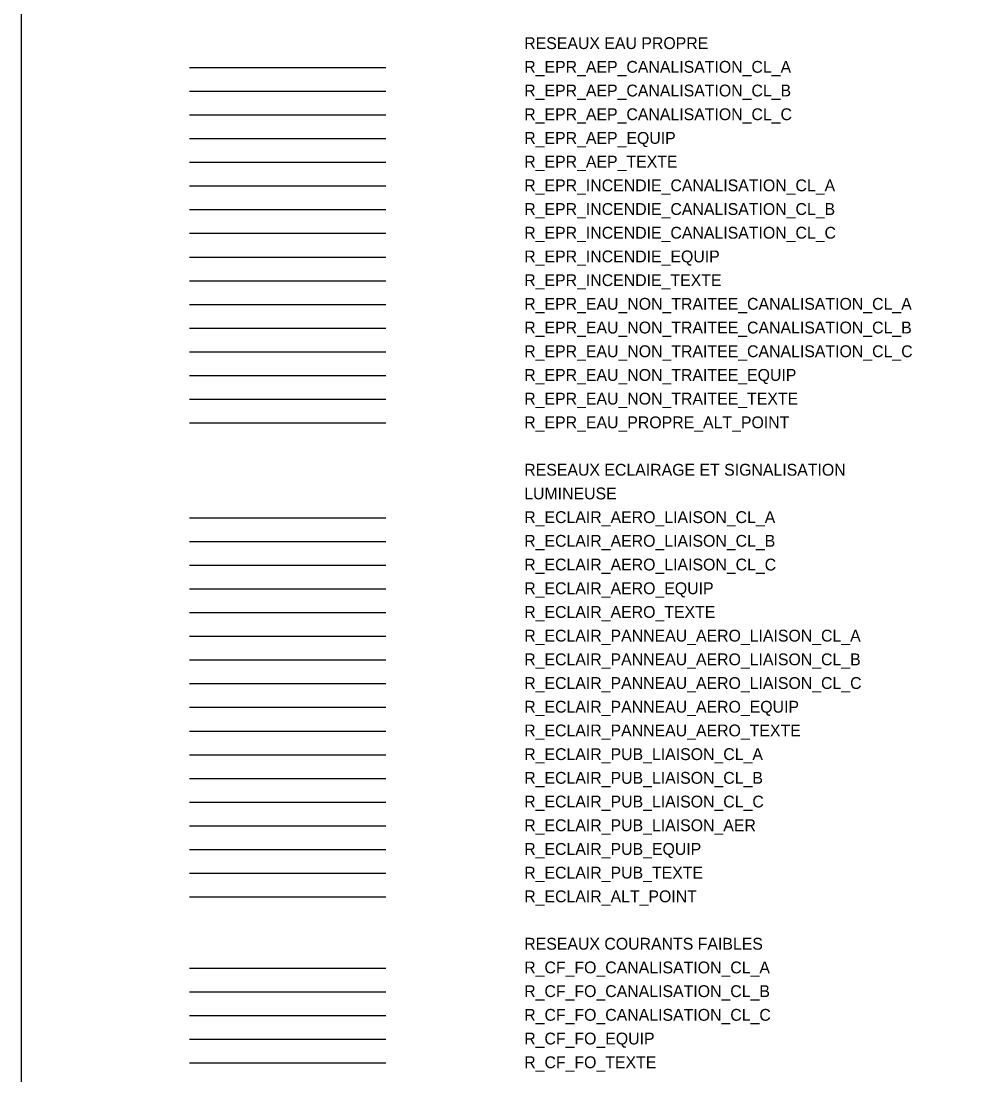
# Model space of a CAD drawing. Extents: x -60 to 214, y -380 to -21.
# Drawn here: x 33.07 to 72.77, y -245.94 to -201.47 of the extents above; entities that cross this region are included whole.
import ezdxf

# ---------------------------------------------------------------- set-up
doc = ezdxf.new("R2010")
doc.units = 0
for name, color, linetype in [('Default', 7, 'Continuous'), ('DH_TEXTE', 7, 'Continuous'), ('R_CF_FO_CANALISATION_CL_A', 7, 'Continuous'), ('R_CF_FO_CANALISATION_CL_B', 7, 'Continuous'), ('R_CF_FO_CANALISATION_CL_C', 7, 'Continuous'), ('R_CF_FO_EQUIP', 7, 'Continuous'), ('R_CF_FO_TEXTE', 7, 'Continuous'), ('R_ECLAIR_AERO_EQUIP', 7, 'Continuous'), ('R_ECLAIR_AERO_LIAISON_CL_A', 7, 'Continuous'), ('R_ECLAIR_AERO_LIAISON_CL_B', 7, 'Continuous'), ('R_ECLAIR_AERO_LIAISON_CL_C', 7, 'Continuous'), ('R_ECLAIR_AERO_TEXTE', 7, 'Continuous'), ('R_ECLAIR_ALT_POINT', 7, 'Continuous'), ('R_ECLAIR_PANNEAU_AERO_EQUIP', 7, 'Continuous'), ('R_ECLAIR_PANNEAU_AERO_LIAISON_CL_A', 7, 'Continuous'), ('R_ECLAIR_PANNEAU_AERO_LIAISON_CL_B', 7, 'Continuous'), ('R_ECLAIR_PANNEAU_AERO_LIAISON_CL_C', 7, 'Continuous'), ('R_ECLAIR_PANNEAU_AERO_TEXTE', 7, 'Continuous'), ('R_ECLAIR_PUB_EQUIP', 7, 'Continuous'), ('R_ECLAIR_PUB_LIAISON_CL_A', 7, 'Continuous'), ('R_ECLAIR_PUB_LIAISON_CL_B', 7, 'Continuous'), ('R_ECLAIR_PUB_LIAISON_CL_C', 7, 'Continuous'), ('R_ECLAIR_PUB_TEXTE', 7, 'Continuous'), ('R_EPR_AEP_CANALISATION_CL_A', 7, 'Continuous'), ('R_EPR_AEP_CANALISATION_CL_B', 7, 'Continuous'), ('R_EPR_AEP_CANALISATION_CL_C', 7, 'Continuous'), ('R_EPR_AEP_EQUIP', 7, 'Continuous'), ('R_EPR_AEP_TEXTE', 7, 'Continuous'), ('R_EPR_EAU_NON_TRAITEE_CANALISATION_CL_A', 7, 'Continuous'), ('R_EPR_EAU_NON_TRAITEE_CANALISATION_CL_B', 7, 'Continuous'), ('R_EPR_EAU_NON_TRAITEE_CANALISATION_CL_C', 7, 'Continuous'), ('R_EPR_EAU_NON_TRAITEE_EQUIP', 7, 'Continuous'), ('R_EPR_EAU_NON_TRAITEE_TEXTE', 7, 'Continuous'), ('R_EPR_EAU_PROPRE_ALT_POINT', 7, 'Continuous'), ('R_EPR_INCENDIE_CANALISATION_CL_A', 7, 'Continuous'), ('R_EPR_INCENDIE_CANALISATION_CL_B', 7, 'Continuous'), ('R_EPR_INCENDIE_CANALISATION_CL_C', 7, 'Continuous'), ('R_EPR_INCENDIE_EQUIP', 7, 'Continuous'), ('R_EPR_INCENDIE_TEXTE', 7, 'Continuous')]:
    doc.layers.add(name, color=color, linetype=linetype)

msp = doc.modelspace()

# ---------------------------------------------------------------- linework, layer by layer
at = {"layer": 'Default'}
msp.add_line((40.178, -235.429), (48.457, -235.429), dxfattribs=at)
msp.add_lwpolyline([(114.838, -25.727), (33.073, -25.727), (33.073, -380.216), (114.838, -380.216)], close=True, dxfattribs=at)
at = {"layer": 'R_CF_FO_CANALISATION_CL_A'}
msp.add_line((40.178, -241.429), (48.457, -241.429), dxfattribs=at)
at = {"layer": 'R_CF_FO_CANALISATION_CL_B'}
msp.add_line((40.178, -242.429), (48.457, -242.429), dxfattribs=at)
at = {"layer": 'R_CF_FO_CANALISATION_CL_C'}
msp.add_line((40.178, -243.429), (48.457, -243.429), dxfattribs=at)
at = {"layer": 'R_CF_FO_EQUIP'}
msp.add_line((40.178, -244.429), (48.457, -244.429), dxfattribs=at)
at = {"layer": 'R_CF_FO_TEXTE'}
msp.add_line((40.178, -245.429), (48.457, -245.429), dxfattribs=at)
at = {"layer": 'R_ECLAIR_AERO_EQUIP'}
msp.add_line((40.178, -225.429), (48.457, -225.429), dxfattribs=at)
at = {"layer": 'R_ECLAIR_AERO_LIAISON_CL_A'}
msp.add_line((40.178, -222.429), (48.457, -222.429), dxfattribs=at)
at = {"layer": 'R_ECLAIR_AERO_LIAISON_CL_B'}
msp.add_line((40.178, -223.429), (48.457, -223.429), dxfattribs=at)
at = {"layer": 'R_ECLAIR_AERO_LIAISON_CL_C'}
msp.add_line((40.178, -224.429), (48.457, -224.429), dxfattribs=at)
at = {"layer": 'R_ECLAIR_AERO_TEXTE'}
msp.add_line((40.178, -226.429), (48.457, -226.429), dxfattribs=at)
at = {"layer": 'R_ECLAIR_ALT_POINT'}
msp.add_line((40.178, -238.429), (48.457, -238.429), dxfattribs=at)
at = {"layer": 'R_ECLAIR_PANNEAU_AERO_EQUIP'}
msp.add_line((40.178, -230.429), (48.457, -230.429), dxfattribs=at)
at = {"layer": 'R_ECLAIR_PANNEAU_AERO_LIAISON_CL_A'}
msp.add_line((40.178, -227.429), (48.457, -227.429), dxfattribs=at)
at = {"layer": 'R_ECLAIR_PANNEAU_AERO_LIAISON_CL_B'}
msp.add_line((40.178, -228.429), (48.457, -228.429), dxfattribs=at)
at = {"layer": 'R_ECLAIR_PANNEAU_AERO_LIAISON_CL_C'}
msp.add_line((40.178, -229.429), (48.457, -229.429), dxfattribs=at)
at = {"layer": 'R_ECLAIR_PANNEAU_AERO_TEXTE'}
msp.add_line((40.178, -231.429), (48.457, -231.429), dxfattribs=at)
at = {"layer": 'R_ECLAIR_PUB_EQUIP'}
msp.add_line((40.178, -236.429), (48.457, -236.429), dxfattribs=at)
at = {"layer": 'R_ECLAIR_PUB_LIAISON_CL_A'}
msp.add_line((40.178, -232.429), (48.457, -232.429), dxfattribs=at)
at = {"layer": 'R_ECLAIR_PUB_LIAISON_CL_B'}
msp.add_line((40.178, -233.429), (48.457, -233.429), dxfattribs=at)
at = {"layer": 'R_ECLAIR_PUB_LIAISON_CL_C'}
msp.add_line((40.178, -234.429), (48.457, -234.429), dxfattribs=at)
at = {"layer": 'R_ECLAIR_PUB_TEXTE'}
msp.add_line((40.178, -237.429), (48.457, -237.429), dxfattribs=at)
at = {"layer": 'R_EPR_AEP_CANALISATION_CL_A'}
msp.add_line((40.178, -203.429), (48.457, -203.429), dxfattribs=at)
at = {"layer": 'R_EPR_AEP_CANALISATION_CL_B'}
msp.add_line((40.178, -204.429), (48.457, -204.429), dxfattribs=at)
at = {"layer": 'R_EPR_AEP_CANALISATION_CL_C'}
msp.add_line((40.178, -205.429), (48.457, -205.429), dxfattribs=at)
at = {"layer": 'R_EPR_AEP_EQUIP'}
msp.add_line((40.178, -206.429), (48.457, -206.429), dxfattribs=at)
at = {"layer": 'R_EPR_AEP_TEXTE'}
msp.add_line((40.178, -207.429), (48.457, -207.429), dxfattribs=at)
at = {"layer": 'R_EPR_EAU_NON_TRAITEE_CANALISATION_CL_A'}
msp.add_line((40.178, -213.429), (48.457, -213.429), dxfattribs=at)
at = {"layer": 'R_EPR_EAU_NON_TRAITEE_CANALISATION_CL_B'}
msp.add_line((40.178, -214.429), (48.457, -214.429), dxfattribs=at)
at = {"layer": 'R_EPR_EAU_NON_TRAITEE_CANALISATION_CL_C'}
msp.add_line((40.178, -215.429), (48.457, -215.429), dxfattribs=at)
at = {"layer": 'R_EPR_EAU_NON_TRAITEE_EQUIP'}
msp.add_line((40.178, -216.429), (48.457, -216.429), dxfattribs=at)
at = {"layer": 'R_EPR_EAU_NON_TRAITEE_TEXTE'}
msp.add_line((40.178, -217.429), (48.457, -217.429), dxfattribs=at)
at = {"layer": 'R_EPR_EAU_PROPRE_ALT_POINT'}
msp.add_line((40.178, -218.429), (48.457, -218.429), dxfattribs=at)
at = {"layer": 'R_EPR_INCENDIE_CANALISATION_CL_A'}
msp.add_line((40.178, -208.429), (48.457, -208.429), dxfattribs=at)
at = {"layer": 'R_EPR_INCENDIE_CANALISATION_CL_B'}
msp.add_line((40.178, -209.429), (48.457, -209.429), dxfattribs=at)
at = {"layer": 'R_EPR_INCENDIE_CANALISATION_CL_C'}
msp.add_line((40.178, -210.429), (48.457, -210.429), dxfattribs=at)
at = {"layer": 'R_EPR_INCENDIE_EQUIP'}
msp.add_line((40.178, -211.429), (48.457, -211.429), dxfattribs=at)
at = {"layer": 'R_EPR_INCENDIE_TEXTE'}
msp.add_line((40.178, -212.429), (48.457, -212.429), dxfattribs=at)

# ---------------------------------------------------------------- texts
at = {"layer": 'DH_TEXTE'}
for s, p in [('RESEAUX EAU PROPRE ', (54.301, -202.655)), ('RESEAUX ECLAIRAGE ET SIGNALISATION ', (54.301, -220.655)), ('LUMINEUSE ', (54.301, -221.655)), ('R_ECLAIR_PUB_LIAISON_AER ', (54.301, -235.655)), ('RESEAUX COURANTS FAIBLES ', (54.301, -240.655))]:
    msp.add_text(s, height=0.5, dxfattribs=at).set_placement(p)
at = {"layer": 'R_CF_FO_CANALISATION_CL_A'}
msp.add_text('R_CF_FO_CANALISATION_CL_A ', height=0.5, dxfattribs=at).set_placement((54.301, -241.655))
at = {"layer": 'R_CF_FO_CANALISATION_CL_B'}
msp.add_text('R_CF_FO_CANALISATION_CL_B ', height=0.5, dxfattribs=at).set_placement((54.301, -242.655))
at = {"layer": 'R_CF_FO_CANALISATION_CL_C'}
msp.add_text('R_CF_FO_CANALISATION_CL_C ', height=0.5, dxfattribs=at).set_placement((54.301, -243.655))
at = {"layer": 'R_CF_FO_EQUIP'}
msp.add_text('R_CF_FO_EQUIP ', height=0.5, dxfattribs=at).set_placement((54.301, -244.655))
at = {"layer": 'R_CF_FO_TEXTE'}
msp.add_text('R_CF_FO_TEXTE ', height=0.5, dxfattribs=at).set_placement((54.301, -245.655))
at = {"layer": 'R_ECLAIR_AERO_EQUIP'}
msp.add_text('R_ECLAIR_AERO_EQUIP ', height=0.5, dxfattribs=at).set_placement((54.301, -225.655))
at = {"layer": 'R_ECLAIR_AERO_LIAISON_CL_A'}
msp.add_text('R_ECLAIR_AERO_LIAISON_CL_A ', height=0.5, dxfattribs=at).set_placement((54.301, -222.655))
at = {"layer": 'R_ECLAIR_AERO_LIAISON_CL_B'}
msp.add_text('R_ECLAIR_AERO_LIAISON_CL_B ', height=0.5, dxfattribs=at).set_placement((54.301, -223.655))
at = {"layer": 'R_ECLAIR_AERO_LIAISON_CL_C'}
msp.add_text('R_ECLAIR_AERO_LIAISON_CL_C ', height=0.5, dxfattribs=at).set_placement((54.301, -224.655))
at = {"layer": 'R_ECLAIR_AERO_TEXTE'}
msp.add_text('R_ECLAIR_AERO_TEXTE ', height=0.5, dxfattribs=at).set_placement((54.301, -226.655))
at = {"layer": 'R_ECLAIR_ALT_POINT'}
msp.add_text('R_ECLAIR_ALT_POINT  ', height=0.5, dxfattribs=at).set_placement((54.301, -238.655))
at = {"layer": 'R_ECLAIR_PANNEAU_AERO_EQUIP'}
msp.add_text('R_ECLAIR_PANNEAU_AERO_EQUIP ', height=0.5, dxfattribs=at).set_placement((54.301, -230.655))
at = {"layer": 'R_ECLAIR_PANNEAU_AERO_LIAISON_CL_A'}
msp.add_text('R_ECLAIR_PANNEAU_AERO_LIAISON_CL_A ', height=0.5, dxfattribs=at).set_placement((54.301, -227.655))
at = {"layer": 'R_ECLAIR_PANNEAU_AERO_LIAISON_CL_B'}
msp.add_text('R_ECLAIR_PANNEAU_AERO_LIAISON_CL_B ', height=0.5, dxfattribs=at).set_placement((54.301, -228.655))
at = {"layer": 'R_ECLAIR_PANNEAU_AERO_LIAISON_CL_C'}
msp.add_text('R_ECLAIR_PANNEAU_AERO_LIAISON_CL_C ', height=0.5, dxfattribs=at).set_placement((54.301, -229.655))
at = {"layer": 'R_ECLAIR_PANNEAU_AERO_TEXTE'}
msp.add_text('R_ECLAIR_PANNEAU_AERO_TEXTE ', height=0.5, dxfattribs=at).set_placement((54.301, -231.655))
at = {"layer": 'R_ECLAIR_PUB_EQUIP'}
msp.add_text('R_ECLAIR_PUB_EQUIP ', height=0.5, dxfattribs=at).set_placement((54.301, -236.655))
at = {"layer": 'R_ECLAIR_PUB_LIAISON_CL_A'}
msp.add_text('R_ECLAIR_PUB_LIAISON_CL_A ', height=0.5, dxfattribs=at).set_placement((54.301, -232.655))
at = {"layer": 'R_ECLAIR_PUB_LIAISON_CL_B'}
msp.add_text('R_ECLAIR_PUB_LIAISON_CL_B ', height=0.5, dxfattribs=at).set_placement((54.301, -233.655))
at = {"layer": 'R_ECLAIR_PUB_LIAISON_CL_C'}
msp.add_text('R_ECLAIR_PUB_LIAISON_CL_C ', height=0.5, dxfattribs=at).set_placement((54.301, -234.655))
at = {"layer": 'R_ECLAIR_PUB_TEXTE'}
msp.add_text('R_ECLAIR_PUB_TEXTE ', height=0.5, dxfattribs=at).set_placement((54.301, -237.655))
at = {"layer": 'R_EPR_AEP_CANALISATION_CL_A'}
msp.add_text('R_EPR_AEP_CANALISATION_CL_A ', height=0.5, dxfattribs=at).set_placement((54.301, -203.655))
at = {"layer": 'R_EPR_AEP_CANALISATION_CL_B'}
msp.add_text('R_EPR_AEP_CANALISATION_CL_B ', height=0.5, dxfattribs=at).set_placement((54.301, -204.655))
at = {"layer": 'R_EPR_AEP_CANALISATION_CL_C'}
msp.add_text('R_EPR_AEP_CANALISATION_CL_C ', height=0.5, dxfattribs=at).set_placement((54.301, -205.655))
at = {"layer": 'R_EPR_AEP_EQUIP'}
msp.add_text('R_EPR_AEP_EQUIP ', height=0.5, dxfattribs=at).set_placement((54.301, -206.655))
at = {"layer": 'R_EPR_AEP_TEXTE'}
msp.add_text('R_EPR_AEP_TEXTE ', height=0.5, dxfattribs=at).set_placement((54.301, -207.655))
at = {"layer": 'R_EPR_EAU_NON_TRAITEE_CANALISATION_CL_A'}
msp.add_text('R_EPR_EAU_NON_TRAITEE_CANALISATION_CL_A ', height=0.5, dxfattribs=at).set_placement((54.301, -213.655))
at = {"layer": 'R_EPR_EAU_NON_TRAITEE_CANALISATION_CL_B'}
msp.add_text('R_EPR_EAU_NON_TRAITEE_CANALISATION_CL_B ', height=0.5, dxfattribs=at).set_placement((54.301, -214.655))
at = {"layer": 'R_EPR_EAU_NON_TRAITEE_CANALISATION_CL_C'}
msp.add_text('R_EPR_EAU_NON_TRAITEE_CANALISATION_CL_C ', height=0.5, dxfattribs=at).set_placement((54.301, -215.655))
at = {"layer": 'R_EPR_EAU_NON_TRAITEE_EQUIP'}
msp.add_text('R_EPR_EAU_NON_TRAITEE_EQUIP ', height=0.5, dxfattribs=at).set_placement((54.301, -216.655))
at = {"layer": 'R_EPR_EAU_NON_TRAITEE_TEXTE'}
msp.add_text('R_EPR_EAU_NON_TRAITEE_TEXTE ', height=0.5, dxfattribs=at).set_placement((54.301, -217.655))
at = {"layer": 'R_EPR_EAU_PROPRE_ALT_POINT'}
msp.add_text('R_EPR_EAU_PROPRE_ALT_POINT  ', height=0.5, dxfattribs=at).set_placement((54.301, -218.655))
at = {"layer": 'R_EPR_INCENDIE_CANALISATION_CL_A'}
msp.add_text('R_EPR_INCENDIE_CANALISATION_CL_A ', height=0.5, dxfattribs=at).set_placement((54.301, -208.655))
at = {"layer": 'R_EPR_INCENDIE_CANALISATION_CL_B'}
msp.add_text('R_EPR_INCENDIE_CANALISATION_CL_B ', height=0.5, dxfattribs=at).set_placement((54.301, -209.655))
at = {"layer": 'R_EPR_INCENDIE_CANALISATION_CL_C'}
msp.add_text('R_EPR_INCENDIE_CANALISATION_CL_C ', height=0.5, dxfattribs=at).set_placement((54.301, -210.655))
at = {"layer": 'R_EPR_INCENDIE_EQUIP'}
msp.add_text('R_EPR_INCENDIE_EQUIP ', height=0.5, dxfattribs=at).set_placement((54.301, -211.655))
at = {"layer": 'R_EPR_INCENDIE_TEXTE'}
msp.add_text('R_EPR_INCENDIE_TEXTE ', height=0.5, dxfattribs=at).set_placement((54.301, -212.655))

doc.saveas('drawing.dxf')
